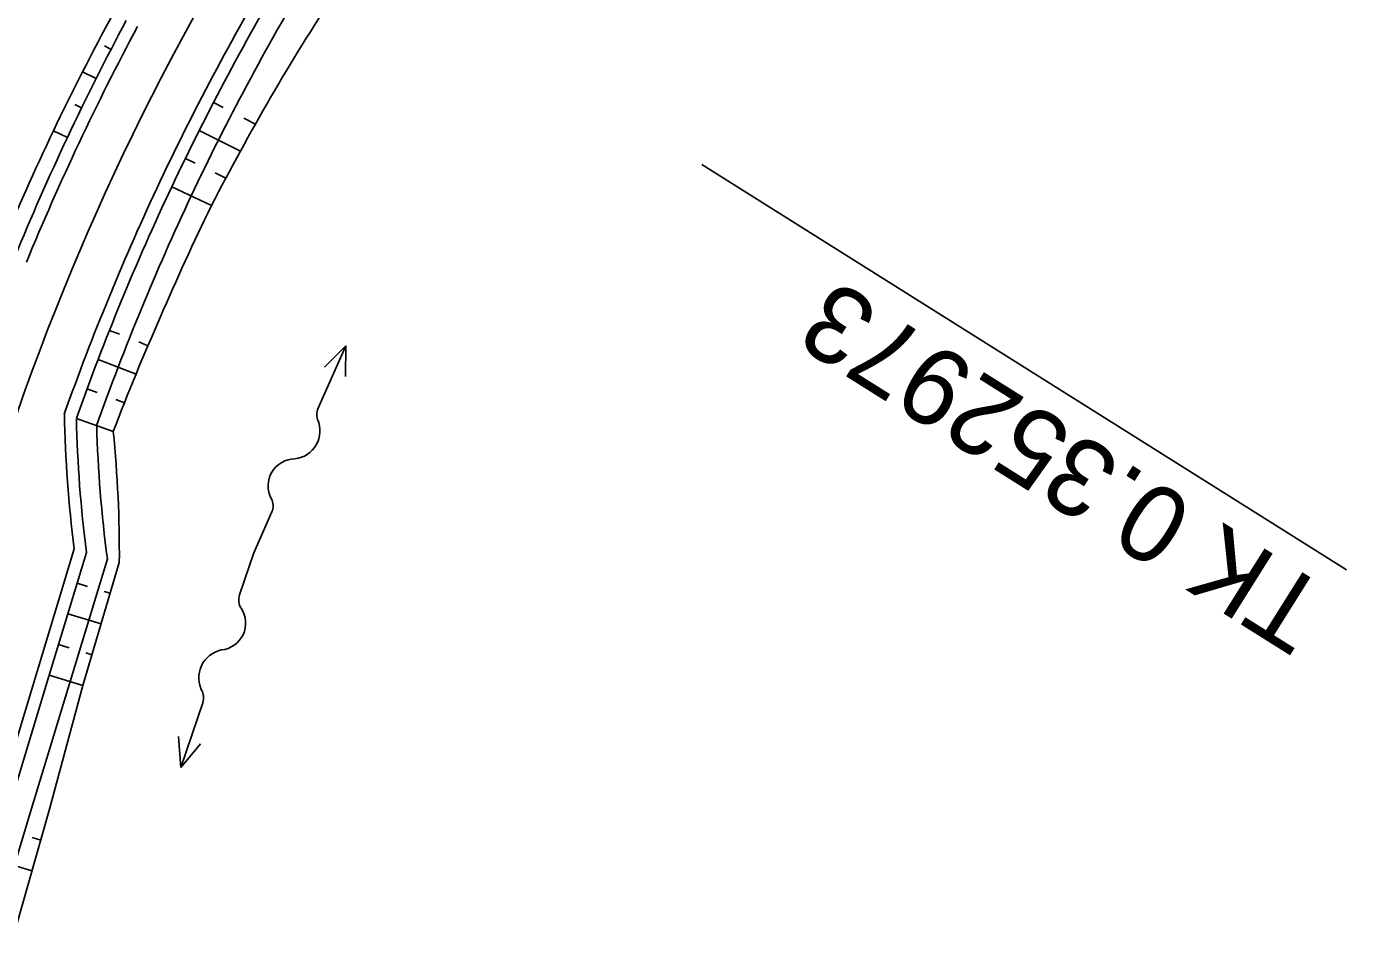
# Model space of a CAD drawing. Extents: x -481656 to -478728, y -1113199 to -1110710.
# Drawn here: x -479575.4 to -479524, y -1112726.4 to -1112691.1 of the extents above; entities that cross this region are included whole.
import ezdxf

# ---------------------------------------------------------------- set-up
doc = ezdxf.new("R2010")
doc.units = 0
for name, color, linetype in [('C1_HATCH_SLOPE_L', 7, 'Continuous'), ('C1_HATCH_SLOPE_R', 7, 'Continuous'), ('C1_HLBODY', 7, 'Continuous'), ('C1_HRANA_TELESO', 7, 'Continuous'), ('C1_KORUNA', 7, 'Continuous'), ('C1_OSA', 7, 'Continuous'), ('C1_PRIKOP', 7, 'Continuous'), ('C1_VOZOVKA', 7, 'Continuous'), ('C1_ZPEVKRAJ', 7, 'Continuous'), ('DRENÁŽ', 7, 'Continuous'), ('PLYN', 7, 'Continuous')]:
    doc.layers.add(name, color=color, linetype=linetype)

# ---------------------------------------------------------------- blocks, each defined once
blk = doc.blocks.new('A$C70B')
at = {"layer": 'DRENÁŽ'}
for p, q in [((0.869, 0.002), (-0.869, -0.002)), ((6.861, 0.426), (7.971, -0.002)), ((7.971, -0.002), (5.275, -0.002)), ((7.971, -0.002), (6.862, -0.478))]:
    blk.add_line(p, q, dxfattribs=at)
for centre, radius, start, end in [((2.168, -0.416), 1.055, 24.4039, 142.0836), ((0.872, 0.584), 0.582, 269.6924, 322.7901), ((4.08, 0.589), 1.109, 210.8873, 317.3707), ((5.319, -0.636), 0.636, 85.9766, 131.7248)]:
    blk.add_arc(centre, radius, start, end, dxfattribs=at)

msp = doc.modelspace()

# ---------------------------------------------------------------- linework, layer by layer
at = {"layer": 'C1_HATCH_SLOPE_L'}
for p, q in [((-479568.149, -1112694.017), (-479567.778, -1112694.21)), ((-479566.962, -1112694.633), (-479566.517, -1112694.863)), ((-479568.705, -1112695.106), (-479567.1, -1112695.912)), ((-479569.247, -1112696.201), (-479568.87, -1112696.384)), ((-479568.082, -1112696.768), (-479567.67, -1112696.969)), ((-479569.775, -1112697.303), (-479568.227, -1112698.033)), ((-479572.207, -1112702.906), (-479571.818, -1112703.06)), ((-479571.067, -1112703.359), (-479570.706, -1112703.503)), ((-479572.651, -1112704.044), (-479571.171, -1112704.611)), ((-479573.081, -1112705.188), (-479572.688, -1112705.333)), ((-479571.958, -1112705.602), (-479571.622, -1112705.726)), ((-479573.496, -1112706.337), (-479572.06, -1112706.846)), ((-479573.466, -1112712.767), (-479573.059, -1112712.89)), ((-479572.415, -1112713.086), (-479572.178, -1112713.158)), ((-479573.828, -1112713.963), (-479572.532, -1112714.357)), ((-479574.191, -1112715.16), (-479573.784, -1112715.284)), ((-479573.132, -1112715.481), (-479572.887, -1112715.555)), ((-479574.554, -1112716.356), (-479573.241, -1112716.754)), ((-479575.222, -1112722.684), (-479574.889, -1112722.785)), ((-479576.731, -1112723.533), (-479575.23, -1112723.988))]:
    msp.add_line(p, q, dxfattribs=at)
at = {"layer": 'C1_HATCH_SLOPE_R'}
for p, q in [((-479572.663, -1112691.678), (-479572.663, -1112691.678)), ((-479572.144, -1112691.947), (-479572.404, -1112691.812)), ((-479572.725, -1112693.085), (-479573.254, -1112692.819)), ((-479573.831, -1112693.968), (-479573.831, -1112693.968)), ((-479573.292, -1112694.23), (-479573.562, -1112694.099)), ((-479573.845, -1112695.383), (-479574.394, -1112695.124))]:
    msp.add_line(p, q, dxfattribs=at)
at = {"layer": 'C1_HLBODY'}
msp.add_line((-479523.956, -1112712.241), (-479549.104, -1112696.44), dxfattribs=at)
at = {"layer": 'C1_HRANA_TELESO'}
for p, q in [((-479571.823, -1112711.959), (-479573.241, -1112716.754)), ((-479573.241, -1112716.754), (-479574.548, -1112721.583)), ((-479574.548, -1112721.583), (-479575.912, -1112726.394))]:
    msp.add_line(p, q, dxfattribs=at)
for centre, radius, start, end in [((-479483.185, -1112742.076), 95.78, 146.88158, 149.74836), ((-479481.642, -1112739.549), 102.842, 151.54244, 154.40728), ((-479482.933, -1112741.989), 95.954, 149.86945, 152.73601), ((-479481.554, -1112739.428), 102.869, 154.48923, 157.35405), ((-479481.909, -1112740.21), 96.071, 153.95856, 156.82362), ((-479482.265, -1112741.266), 96.165, 156.16196, 159.02767), ((-479619.935, -1112711.626), 48.113, 359.6032, 5.7011)]:
    msp.add_arc(centre, radius, start, end, dxfattribs=at)
at = {"layer": 'C1_KORUNA'}
for p, q in [((-479573.103, -1112711.571), (-479574.554, -1112716.356)), ((-479574.554, -1112716.356), (-479576.005, -1112721.141))]:
    msp.add_line(p, q, dxfattribs=at)
for centre, radius, start, end in [((-479481.366, -1112739.002), 97.75, 149.01874, 151.88353), ((-479481.366, -1112739.002), 102.25, 151.88353, 154.74832), ((-479481.366, -1112739.002), 97.75, 151.88353, 154.74832), ((-479481.366, -1112739.002), 102.25, 154.74832, 157.61311), ((-479481.366, -1112739.002), 97.75, 154.74832, 157.61311), ((-479481.366, -1112739.002), 97.75, 157.61311, 160.4779), ((-479524.632, -1112705.297), 48.875, 181.2201, 187.3759)]:
    msp.add_arc(centre, radius, start, end, dxfattribs=at)
at = {"layer": 'C1_OSA'}
msp.add_arc((-479481.366, -1112739.002), 100, 147.85753, 163.12732, dxfattribs=at)
at = {"layer": 'C1_PRIKOP'}
for p, q in [((-479572.289, -1112711.818), (-479573.74, -1112716.603)), ((-479573.74, -1112716.603), (-479575.191, -1112721.387)), ((-479575.191, -1112721.387), (-479576.642, -1112726.172))]:
    msp.add_line(p, q, dxfattribs=at)
for centre, radius, start, end in [((-479481.366, -1112739.002), 96.912, 149.01874, 151.88353), ((-479481.366, -1112739.002), 96.912, 151.88353, 154.74832), ((-479481.366, -1112739.002), 96.912, 154.74832, 157.61311), ((-479481.366, -1112739.002), 96.912, 157.61311, 160.4779), ((-479524.267, -1112705.342), 48.456, 181.5075, 187.6799)]:
    msp.add_arc(centre, radius, start, end, dxfattribs=at)
at = {"layer": 'C1_VOZOVKA'}
for p, q in [((-479573.581, -1112711.426), (-479575.032, -1112716.211)), ((-479575.032, -1112716.211), (-479576.484, -1112720.995))]:
    msp.add_line(p, q, dxfattribs=at)
for centre, radius, start, end in [((-479481.366, -1112739.002), 98.25, 149.01874, 151.88353), ((-479481.366, -1112739.002), 101.75, 151.88353, 154.74832), ((-479481.366, -1112739.002), 98.25, 151.88353, 154.74832), ((-479481.366, -1112739.002), 101.75, 154.74832, 157.61311), ((-479481.366, -1112739.002), 98.25, 154.74832, 157.61311), ((-479481.366, -1112739.002), 98.25, 157.61311, 160.4779), ((-479524.852, -1112705.204), 49.125, 181.1271, 187.2766)]:
    msp.add_arc(centre, radius, start, end, dxfattribs=at)
at = {"layer": 'C1_ZPEVKRAJ'}
for p, q in [((-479573.581, -1112711.426), (-479575.032, -1112716.211)), ((-479575.032, -1112716.211), (-479576.484, -1112720.995))]:
    msp.add_line(p, q, dxfattribs=at)
for centre, radius, start, end in [((-479481.366, -1112739.002), 98.25, 149.01874, 151.88353), ((-479481.366, -1112739.002), 101.75, 151.88353, 154.74832), ((-479481.366, -1112739.002), 98.25, 151.88353, 154.74832), ((-479481.366, -1112739.002), 101.75, 154.74832, 157.61311), ((-479481.366, -1112739.002), 98.25, 154.74832, 157.61311), ((-479481.366, -1112739.002), 98.25, 157.61311, 160.4779), ((-479524.852, -1112705.204), 49.125, 181.1271, 187.2766)]:
    msp.add_arc(centre, radius, start, end, dxfattribs=at)

# ---------------------------------------------------------------- block references
at = {"layer": 'PLYN'}
for p, rotation in [((-479566.229, -1112710.784), 65.97796761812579), ((-479566.859, -1112712.402), -108.74310621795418)]:
    msp.add_blockref('A$C70B', p, dxfattribs=dict(at, rotation=rotation))

# ---------------------------------------------------------------- texts
at = {"layer": 'C1_HLBODY'}
msp.add_text('TK 0.352973', height=3, rotation=147.8575, dxfattribs=at).set_placement((-479524.487, -1112713.089))

doc.saveas('drawing.dxf')
